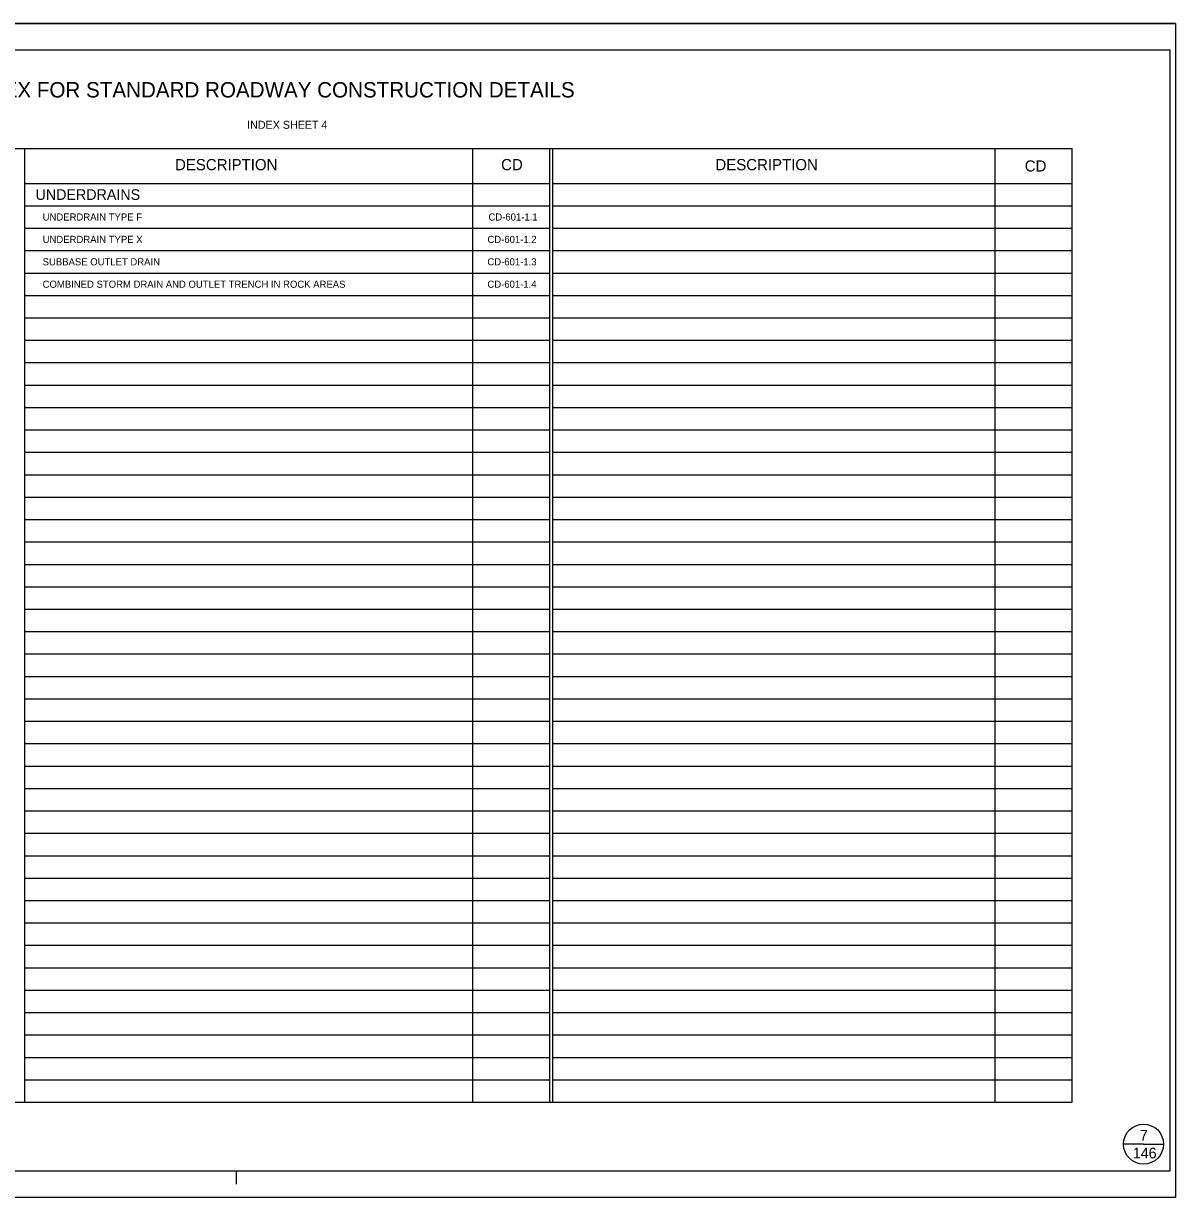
# Model space of a CAD drawing. Extents: x 503613 to 504661, y 498262 to 498922.
# Drawn here: x 504013 to 504661, y 498262 to 498922 of the extents above; entities that cross this region are included whole.
import ezdxf

# ---------------------------------------------------------------- set-up
doc = ezdxf.new("R2010")
doc.units = 0
for name, color, linetype in [('1', 7, 'Continuous'), ('39', 7, 'Continuous'), ('41', 7, 'Continuous')]:
    doc.layers.add(name, color=color, linetype=linetype)

msp = doc.modelspace()

# ---------------------------------------------------------------- linework, layer by layer
at = {"layer": '1'}
for p, q in [((504661.22, 498922.31), (503613.04, 498922.31)), ((504658.22, 498907.31), (503668.22, 498907.31)), ((504658.22, 498277.31), (504658.22, 498907.31)), ((503717.27, 498852.12), (504603.1, 498852.12)), ((504014.12, 498315.9), (504014.12, 498852.12)), ((504014.12, 498832.43), (504014.12, 498852.12)), ((504266.09, 498315.9), (504266.09, 498852.12)), ((504266.09, 498832.43), (504266.09, 498852.12)), ((504309.4, 498315.9), (504309.4, 498852.12)), ((504309.4, 498832.43), (504309.4, 498852.12)), ((504310.97, 498315.9), (504310.97, 498852.12)), ((504310.97, 498832.43), (504310.97, 498852.12)), ((504559.79, 498315.9), (504559.79, 498852.12)), ((504559.79, 498832.43), (504559.79, 498852.12)), ((504603.1, 498315.9), (504603.1, 498852.12)), ((504603.1, 498832.43), (504603.1, 498852.12)), ((504014.12, 498832.43), (504309.4, 498832.43)), ((504310.97, 498832.43), (504603.1, 498832.43)), ((504335.38, 498832.43), (504603.1, 498832.43)), ((504014.12, 498819.83), (504309.4, 498819.83)), ((504310.97, 498819.83), (504603.1, 498819.83)), ((504014.12, 498807.24), (504309.4, 498807.24)), ((504310.97, 498807.24), (504603.1, 498807.24)), ((504014.12, 498794.64), (504309.4, 498794.64)), ((504310.97, 498794.64), (504603.1, 498794.64)), ((504014.12, 498782.04), (504309.4, 498782.04)), ((504310.97, 498782.04), (504603.1, 498782.04)), ((504014.12, 498769.44), (504309.4, 498769.44)), ((504310.97, 498769.44), (504603.1, 498769.44)), ((504014.12, 498756.84), (504309.4, 498756.84)), ((504310.97, 498756.84), (504603.1, 498756.84)), ((504014.12, 498744.24), (504309.4, 498744.24)), ((504310.97, 498744.24), (504603.1, 498744.24)), ((504014.12, 498731.65), (504309.4, 498731.65)), ((504310.97, 498731.65), (504603.1, 498731.65)), ((504014.12, 498719.05), (504309.4, 498719.05)), ((504310.97, 498719.05), (504603.1, 498719.05)), ((504014.12, 498706.45), (504309.4, 498706.45)), ((504310.97, 498706.45), (504603.1, 498706.45)), ((504014.12, 498693.85), (504309.4, 498693.85)), ((504310.97, 498693.85), (504603.1, 498693.85)), ((504014.12, 498681.25), (504309.4, 498681.25)), ((504310.97, 498681.25), (504603.1, 498681.25)), ((504014.12, 498668.65), (504309.4, 498668.65)), ((504310.97, 498668.65), (504603.1, 498668.65)), ((504014.12, 498656.06), (504309.4, 498656.06)), ((504310.97, 498656.06), (504603.1, 498656.06)), ((504014.12, 498643.46), (504309.4, 498643.46)), ((504310.97, 498643.46), (504603.1, 498643.46)), ((504014.12, 498630.86), (504309.4, 498630.86)), ((504310.97, 498630.86), (504603.1, 498630.86)), ((504014.12, 498618.26), (504309.4, 498618.26)), ((504310.97, 498618.26), (504603.1, 498618.26)), ((504014.12, 498605.66), (504309.4, 498605.66)), ((504310.97, 498605.66), (504603.1, 498605.66)), ((504014.12, 498593.06), (504309.4, 498593.06)), ((504310.97, 498593.06), (504603.1, 498593.06)), ((504014.12, 498580.46), (504309.4, 498580.46)), ((504310.97, 498580.46), (504603.1, 498580.46)), ((504014.12, 498567.87), (504309.4, 498567.87)), ((504310.97, 498567.87), (504603.1, 498567.87)), ((504014.12, 498555.27), (504309.4, 498555.27)), ((504310.97, 498555.27), (504603.1, 498555.27)), ((504014.12, 498542.67), (504309.4, 498542.67)), ((504310.97, 498542.67), (504603.1, 498542.67)), ((504014.12, 498530.07), (504309.4, 498530.07)), ((504310.97, 498530.07), (504603.1, 498530.07)), ((504014.12, 498517.47), (504309.4, 498517.47)), ((504310.97, 498517.47), (504603.1, 498517.47)), ((504014.12, 498504.87), (504309.4, 498504.87)), ((504310.97, 498504.87), (504603.1, 498504.87)), ((504014.12, 498492.28), (504309.4, 498492.28)), ((504310.97, 498492.28), (504603.1, 498492.28)), ((504014.12, 498479.68), (504309.4, 498479.68)), ((504310.97, 498479.68), (504603.1, 498479.68)), ((504014.12, 498467.08), (504309.4, 498467.08)), ((504310.97, 498467.08), (504603.1, 498467.08)), ((504014.12, 498454.48), (504309.4, 498454.48)), ((504310.97, 498454.48), (504603.1, 498454.48)), ((504014.12, 498441.88), (504309.4, 498441.88)), ((504310.97, 498441.88), (504603.1, 498441.88)), ((504014.12, 498429.28), (504309.4, 498429.28)), ((504310.97, 498429.28), (504603.1, 498429.28)), ((504014.12, 498416.68), (504309.4, 498416.68)), ((504310.97, 498416.68), (504603.1, 498416.68)), ((504014.12, 498404.09), (504309.4, 498404.09)), ((504310.97, 498404.09), (504603.1, 498404.09)), ((504014.12, 498391.49), (504309.4, 498391.49)), ((504310.97, 498391.49), (504603.1, 498391.49)), ((504014.12, 498378.89), (504309.4, 498378.89)), ((504310.97, 498378.89), (504603.1, 498378.89)), ((504014.12, 498366.29), (504309.4, 498366.29)), ((504310.97, 498366.29), (504603.1, 498366.29)), ((504014.12, 498353.69), (504309.4, 498353.69)), ((504310.97, 498353.69), (504603.1, 498353.69)), ((504014.12, 498341.09), (504309.4, 498341.09)), ((504310.97, 498341.09), (504603.1, 498341.09)), ((504014.12, 498328.5), (504309.4, 498328.5)), ((504310.97, 498328.5), (504603.1, 498328.5)), ((503717.27, 498315.9), (504603.1, 498315.9)), ((504643.22, 498292.31), (504631.97, 498292.31)), ((504643.22, 498292.31), (504654.47, 498292.31)), ((503668.22, 498277.31), (504658.22, 498277.31)), ((504133.22, 498269.81), (504133.22, 498277.31)), ((504661.22, 498262.31), (503613.04, 498262.31))]:
    msp.add_line(p, q, dxfattribs=at)
msp.add_circle((504643.22, 498292.32), 11.25, dxfattribs=at)
at = {"layer": '41'}
msp.add_lwpolyline([(503613.04, 498922.31), (504661.22, 498922.31), (504661.22, 498262.31), (503613.04, 498262.31)], close=True, dxfattribs=at)

# ---------------------------------------------------------------- texts
at = {"layer": '1'}
for p in [(504098.57, 498839.82), (504402.48, 498839.82)]:
    msp.add_text('DESCRIPTION', height=6.2992, dxfattribs=at).set_placement(p)
at = {"layer": '39'}
for s, height, p in [('INDEX FOR STANDARD ROADWAY CONSTRUCTION DETAILS', 8.6614, (503982.24, 498880.71)), ('INDEX SHEET 4', 4.5, (504139.14, 498863.11)), ('CD', 6.299, (504281.95, 498839.82)), ('CD', 6.299, (504576.44, 498839.06)), ('UNDERDRAINS', 6, (504020.12, 498823.13)), ('UNDERDRAIN TYPE F', 4, (504024.12, 498811.53)), ('CD-601-1.1', 4, (504274.83, 498811.53)), ('UNDERDRAIN TYPE X', 4, (504024.12, 498798.94)), ('CD-601-1.2', 4, (504274.26, 498798.94)), ('SUBBASE OUTLET DRAIN ', 4, (504024.12, 498786.34)), ('CD-601-1.3', 4, (504274.22, 498786.34)), ('COMBINED STORM DRAIN AND OUTLET TRENCH IN ROCK AREAS', 4, (504024.12, 498773.74)), ('CD-601-1.4', 4, (504274.22, 498773.74)), ('7', 6, (504641.15, 498294.31)), ('146', 6, (504637.19, 498284.31))]:
    msp.add_text(s, height=height, dxfattribs=at).set_placement(p)

doc.saveas('drawing.dxf')
